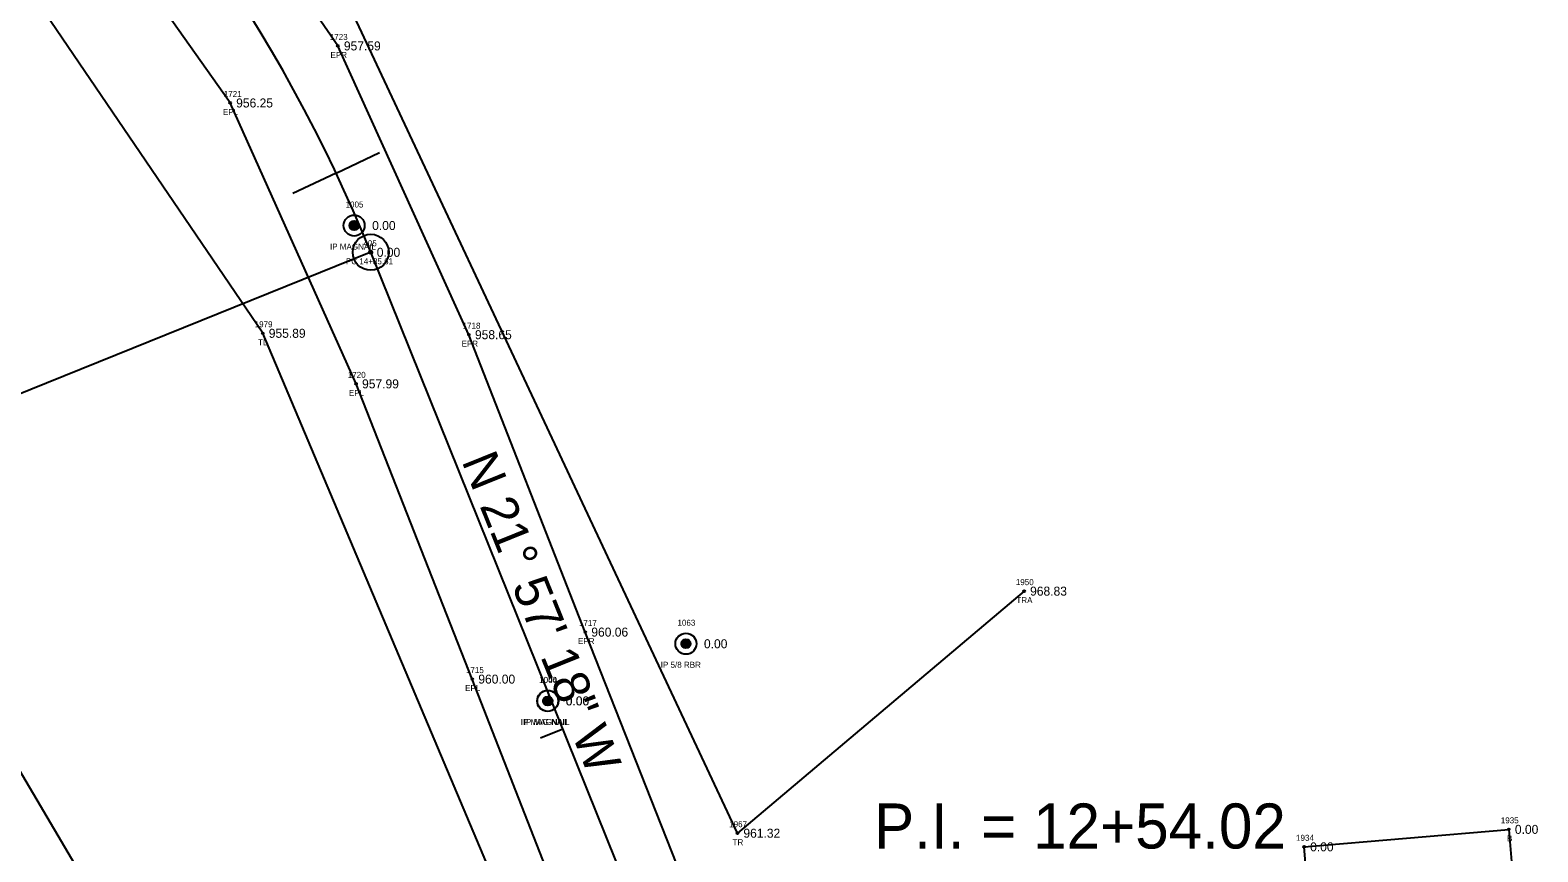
# Model space of a CAD drawing. Extents: x 1528109 to 1531398, y 1157799 to 1162548.
# Drawn here: x 1530505.4 to 1530756.6, y 1158881.4 to 1159018.3 of the extents above; entities that cross this region are included whole.
import ezdxf

# ---------------------------------------------------------------- set-up
doc = ezdxf.new("R2010")
doc.units = 0
for name, color, linetype in [('RD_EX_Bldg', 7, 'Continuous'), ('RD_EX_Bldg_txCode', 7, 'Continuous'), ('RD_EX_DV_Prop_txCode', 7, 'Continuous'), ('RD_EX_DV_PropPin', 7, 'Continuous'), ('RD_EX_Road', 7, 'Continuous'), ('RD_EX_Road_txCode', 7, 'Continuous'), ('RD_EX_TX_Bldg_ELEV', 7, 'Continuous'), ('RD_EX_TX_DV_Prop_ELEV', 7, 'Continuous'), ('RD_EX_TX_Road_ELEV', 7, 'Continuous'), ('RD_EX_TX_VEG_ELEV', 7, 'Continuous'), ('RD_EX_VEG', 7, 'Continuous'), ('RD_EX_VEG_txCode', 7, 'Continuous'), ('RD_HC_Cl', 7, 'Continuous'), ('RD_HC_Data', 7, 'Continuous'), ('RD_HC_Data_Tic', 7, 'Continuous'), ('RD_HC_Survey_ELEV', 7, 'Continuous'), ('RD_HC_txCode', 7, 'Continuous'), ('RD_SMD_Locator', 7, 'Continuous')]:
    doc.layers.add(name, color=color, linetype=linetype)

msp = doc.modelspace()

# ---------------------------------------------------------------- linework, layer by layer
at = {"layer": 'RD_EX_Bldg'}
msp.add_lwpolyline([(1530755.36, 1158841.21), (1530721.26, 1158838.3), (1530717.63, 1158882.28), (1530751.73, 1158885.19), (1530755.36, 1158841.21)], dxfattribs=at)
at = {"layer": 'RD_EX_DV_PropPin'}
for p, q in [((1530558.67, 1158985.55), (1530558.67, 1158985.94)), ((1530558.7, 1158985.45), (1530558.7, 1158986.05)), ((1530558.74, 1158985.38), (1530558.74, 1158986.12)), ((1530558.77, 1158985.32), (1530558.77, 1158986.18)), ((1530558.81, 1158985.27), (1530558.81, 1158986.22)), ((1530558.84, 1158985.23), (1530558.84, 1158986.26)), ((1530558.88, 1158985.2), (1530558.88, 1158986.3)), ((1530558.91, 1158985.17), (1530558.91, 1158986.33)), ((1530558.95, 1158985.14), (1530558.95, 1158986.36)), ((1530558.99, 1158985.11), (1530558.99, 1158986.38)), ((1530559.02, 1158985.09), (1530559.02, 1158986.4)), ((1530559.06, 1158985.07), (1530559.06, 1158986.42)), ((1530559.09, 1158985.06), (1530559.09, 1158986.44)), ((1530559.13, 1158985.04), (1530559.13, 1158986.46)), ((1530559.16, 1158985.03), (1530559.16, 1158986.47)), ((1530559.2, 1158985.02), (1530559.2, 1158986.48)), ((1530559.23, 1158985.01), (1530559.23, 1158986.49)), ((1530559.27, 1158985), (1530559.27, 1158986.5)), ((1530559.3, 1158984.99), (1530559.3, 1158986.5)), ((1530559.34, 1158984.99), (1530559.34, 1158986.51)), ((1530559.37, 1158984.99), (1530559.37, 1158986.51)), ((1530559.41, 1158984.99), (1530559.41, 1158986.51)), ((1530559.44, 1158984.99), (1530559.44, 1158986.51)), ((1530559.48, 1158984.99), (1530559.48, 1158986.51)), ((1530559.51, 1158984.99), (1530559.51, 1158986.5)), ((1530559.55, 1158985), (1530559.55, 1158986.5)), ((1530559.58, 1158985.01), (1530559.58, 1158986.49)), ((1530559.62, 1158985.02), (1530559.62, 1158986.48)), ((1530559.65, 1158985.03), (1530559.65, 1158986.47)), ((1530559.69, 1158985.04), (1530559.69, 1158986.46)), ((1530559.72, 1158985.06), (1530559.72, 1158986.44)), ((1530559.76, 1158985.07), (1530559.76, 1158986.42)), ((1530559.79, 1158985.09), (1530559.79, 1158986.4)), ((1530559.83, 1158985.11), (1530559.83, 1158986.38)), ((1530559.86, 1158985.14), (1530559.86, 1158986.36)), ((1530559.9, 1158985.17), (1530559.9, 1158986.33)), ((1530559.93, 1158985.2), (1530559.93, 1158986.3)), ((1530559.97, 1158985.23), (1530559.97, 1158986.26)), ((1530560, 1158985.27), (1530560, 1158986.22)), ((1530560.04, 1158985.32), (1530560.04, 1158986.18)), ((1530560.07, 1158985.38), (1530560.07, 1158986.12)), ((1530560.11, 1158985.45), (1530560.11, 1158986.05)), ((1530560.14, 1158985.55), (1530560.14, 1158985.94)), ((1530613.93, 1158915.9), (1530613.93, 1158916.3)), ((1530613.97, 1158915.8), (1530613.97, 1158916.4)), ((1530614, 1158915.73), (1530614, 1158916.47)), ((1530614.04, 1158915.67), (1530614.04, 1158916.53)), ((1530614.07, 1158915.63), (1530614.07, 1158916.57)), ((1530614.11, 1158915.59), (1530614.11, 1158916.62)), ((1530614.14, 1158915.55), (1530614.14, 1158916.65)), ((1530614.18, 1158915.52), (1530614.18, 1158916.68)), ((1530614.21, 1158915.49), (1530614.21, 1158916.71)), ((1530614.25, 1158915.47), (1530614.25, 1158916.74)), ((1530614.28, 1158915.44), (1530614.28, 1158916.76)), ((1530614.32, 1158915.42), (1530614.32, 1158916.78)), ((1530614.35, 1158915.41), (1530614.35, 1158916.79)), ((1530614.39, 1158915.39), (1530614.39, 1158916.81)), ((1530614.42, 1158915.38), (1530614.42, 1158916.82)), ((1530614.46, 1158915.37), (1530614.46, 1158916.83)), ((1530614.49, 1158915.36), (1530614.49, 1158916.84)), ((1530614.53, 1158915.35), (1530614.53, 1158916.85)), ((1530614.56, 1158915.35), (1530614.56, 1158916.85)), ((1530614.6, 1158915.34), (1530614.6, 1158916.86)), ((1530614.63, 1158915.34), (1530614.63, 1158916.86)), ((1530614.67, 1158915.34), (1530614.67, 1158916.86)), ((1530614.7, 1158915.34), (1530614.7, 1158916.86)), ((1530614.74, 1158915.34), (1530614.74, 1158916.86)), ((1530614.77, 1158915.35), (1530614.77, 1158916.85)), ((1530614.81, 1158915.35), (1530614.81, 1158916.85)), ((1530614.84, 1158915.36), (1530614.84, 1158916.84)), ((1530614.88, 1158915.37), (1530614.88, 1158916.83)), ((1530614.91, 1158915.38), (1530614.91, 1158916.82)), ((1530614.95, 1158915.39), (1530614.95, 1158916.81)), ((1530614.98, 1158915.41), (1530614.98, 1158916.79)), ((1530615.02, 1158915.42), (1530615.02, 1158916.78)), ((1530615.05, 1158915.44), (1530615.05, 1158916.76)), ((1530615.09, 1158915.47), (1530615.09, 1158916.74)), ((1530615.12, 1158915.49), (1530615.12, 1158916.71)), ((1530615.16, 1158915.52), (1530615.16, 1158916.68)), ((1530615.19, 1158915.55), (1530615.19, 1158916.65)), ((1530615.23, 1158915.59), (1530615.23, 1158916.62)), ((1530615.26, 1158915.63), (1530615.26, 1158916.57)), ((1530615.3, 1158915.67), (1530615.3, 1158916.53)), ((1530615.33, 1158915.73), (1530615.33, 1158916.47)), ((1530615.37, 1158915.8), (1530615.37, 1158916.4)), ((1530615.4, 1158915.9), (1530615.4, 1158916.3)), ((1530591.19, 1158905.97), (1530591.19, 1158907.19)), ((1530591.21, 1158905.97), (1530591.21, 1158907.19)), ((1530591.22, 1158905.94), (1530591.22, 1158907.21)), ((1530591.25, 1158905.95), (1530591.25, 1158907.21)), ((1530591.26, 1158905.92), (1530591.26, 1158907.24)), ((1530591.28, 1158905.92), (1530591.28, 1158907.24)), ((1530591.29, 1158905.9), (1530591.29, 1158907.26)), ((1530591.32, 1158905.9), (1530591.32, 1158907.26)), ((1530591.33, 1158905.89), (1530591.33, 1158907.27)), ((1530591.35, 1158905.89), (1530591.35, 1158907.27)), ((1530591.36, 1158905.87), (1530591.36, 1158907.29)), ((1530591.39, 1158905.87), (1530591.39, 1158907.29)), ((1530591.4, 1158905.86), (1530591.4, 1158907.3)), ((1530591.42, 1158905.86), (1530591.42, 1158907.3)), ((1530591.43, 1158905.85), (1530591.43, 1158907.31)), ((1530591.46, 1158905.85), (1530591.46, 1158907.31)), ((1530591.47, 1158905.84), (1530591.47, 1158907.32)), ((1530591.49, 1158905.84), (1530591.49, 1158907.32)), ((1530591.5, 1158905.83), (1530591.5, 1158907.33)), ((1530591.53, 1158905.83), (1530591.53, 1158907.33)), ((1530591.54, 1158905.83), (1530591.54, 1158907.33)), ((1530591.56, 1158905.83), (1530591.56, 1158907.33)), ((1530591.57, 1158905.82), (1530591.57, 1158907.34)), ((1530591.6, 1158905.82), (1530591.6, 1158907.34)), ((1530591.61, 1158905.82), (1530591.61, 1158907.34)), ((1530591.63, 1158905.82), (1530591.63, 1158907.34)), ((1530591.64, 1158905.82), (1530591.64, 1158907.34)), ((1530591.67, 1158905.82), (1530591.67, 1158907.34)), ((1530591.68, 1158905.82), (1530591.68, 1158907.34)), ((1530591.7, 1158905.82), (1530591.7, 1158907.34)), ((1530591.71, 1158905.82), (1530591.71, 1158907.34)), ((1530591.74, 1158905.82), (1530591.74, 1158907.34)), ((1530591.75, 1158905.83), (1530591.75, 1158907.33)), ((1530591.77, 1158905.83), (1530591.77, 1158907.33)), ((1530591.78, 1158905.83), (1530591.78, 1158907.33)), ((1530591.81, 1158905.83), (1530591.81, 1158907.33)), ((1530591.82, 1158905.84), (1530591.82, 1158907.32)), ((1530591.84, 1158905.84), (1530591.84, 1158907.32)), ((1530591.85, 1158905.85), (1530591.85, 1158907.31)), ((1530591.88, 1158905.85), (1530591.88, 1158907.31)), ((1530591.89, 1158905.86), (1530591.89, 1158907.3)), ((1530591.91, 1158905.86), (1530591.91, 1158907.3)), ((1530591.92, 1158905.87), (1530591.92, 1158907.29)), ((1530591.95, 1158905.87), (1530591.95, 1158907.29)), ((1530591.96, 1158905.89), (1530591.96, 1158907.27)), ((1530591.99, 1158905.89), (1530591.99, 1158907.27)), ((1530591.99, 1158905.9), (1530591.99, 1158907.26)), ((1530592.02, 1158905.9), (1530592.02, 1158907.26)), ((1530592.03, 1158905.92), (1530592.03, 1158907.24)), ((1530592.06, 1158905.92), (1530592.06, 1158907.24)), ((1530592.06, 1158905.94), (1530592.06, 1158907.21)), ((1530592.09, 1158905.95), (1530592.09, 1158907.21)), ((1530592.1, 1158905.97), (1530592.1, 1158907.19)), ((1530592.13, 1158905.97), (1530592.13, 1158907.19)), ((1530590.91, 1158906.38), (1530590.91, 1158906.78)), ((1530590.93, 1158906.38), (1530590.93, 1158906.78)), ((1530590.94, 1158906.28), (1530590.94, 1158906.88)), ((1530590.97, 1158906.28), (1530590.97, 1158906.88)), ((1530590.98, 1158906.21), (1530590.98, 1158906.95)), ((1530591, 1158906.21), (1530591, 1158906.95)), ((1530591.01, 1158906.15), (1530591.01, 1158907.01)), ((1530591.04, 1158906.15), (1530591.04, 1158907.01)), ((1530591.05, 1158906.11), (1530591.05, 1158907.05)), ((1530591.07, 1158906.11), (1530591.07, 1158907.05)), ((1530591.08, 1158906.06), (1530591.08, 1158907.09)), ((1530591.11, 1158906.06), (1530591.11, 1158907.09)), ((1530591.12, 1158906.03), (1530591.12, 1158907.13)), ((1530591.14, 1158906.03), (1530591.14, 1158907.13)), ((1530591.15, 1158906), (1530591.15, 1158907.16)), ((1530591.18, 1158906), (1530591.18, 1158907.16)), ((1530592.13, 1158906), (1530592.13, 1158907.16)), ((1530592.16, 1158906), (1530592.16, 1158907.16)), ((1530592.17, 1158906.03), (1530592.17, 1158907.13)), ((1530592.2, 1158906.03), (1530592.2, 1158907.13)), ((1530592.2, 1158906.06), (1530592.2, 1158907.09)), ((1530592.23, 1158906.06), (1530592.23, 1158907.09)), ((1530592.24, 1158906.11), (1530592.24, 1158907.05)), ((1530592.27, 1158906.11), (1530592.27, 1158907.05)), ((1530592.27, 1158906.15), (1530592.27, 1158907.01)), ((1530592.3, 1158906.15), (1530592.3, 1158907.01)), ((1530592.31, 1158906.21), (1530592.31, 1158906.95)), ((1530592.34, 1158906.21), (1530592.34, 1158906.95)), ((1530592.34, 1158906.28), (1530592.34, 1158906.88)), ((1530592.37, 1158906.28), (1530592.37, 1158906.88)), ((1530592.38, 1158906.38), (1530592.38, 1158906.78)), ((1530592.41, 1158906.38), (1530592.41, 1158906.78))]:
    msp.add_line(p, q, dxfattribs=at)
for centre, radius in [((1530559.41, 1158985.75), 1.75), ((1530559.41, 1158985.75), 0.761), ((1530614.67, 1158916.1), 1.75), ((1530614.67, 1158916.1), 0.761), ((1530591.64, 1158906.58), 1.75), ((1530591.67, 1158906.58), 1.75), ((1530591.64, 1158906.58), 0.761), ((1530591.67, 1158906.58), 0.761)]:
    msp.add_circle(centre, radius, dxfattribs=at)
at = {"layer": 'RD_EX_Road'}
for points in [[(1530704.87, 1158597.47), (1530691.01, 1158649.88), (1530681.22, 1158687.32), (1530670.59, 1158725), (1530654.42, 1158774.07), (1530635.35, 1158823.15), (1530627.8, 1158842.3), (1530617.35, 1158868.69), (1530597.91, 1158918.04), (1530578.53, 1158967.57), (1530556.7, 1159015.66), (1530524.51, 1159062.45), (1530499.94, 1159086.31), (1530481.93, 1159100.12), (1530434.53, 1159127), (1530416.95, 1159134.13), (1530380.01, 1159145.61), (1530337.52, 1159156.44)], [(1530685.41, 1158592.23), (1530678.87, 1158616.46), (1530671.67, 1158642.17), (1530661.52, 1158682.33), (1530651.17, 1158718.79), (1530644.65, 1158739.35), (1530638.95, 1158757.58), (1530635.45, 1158767.4), (1530616.88, 1158814.94), (1530597.61, 1158862.78), (1530579.09, 1158910.21), (1530559.73, 1158959.38), (1530538.76, 1159006.16), (1530508.96, 1159048.3), (1530469.44, 1159083.44), (1530424.03, 1159108.51), (1530374.97, 1159125.76), (1530332.28, 1159136.67)]]:
    msp.add_lwpolyline(points, dxfattribs=at)
at = {"layer": 'RD_EX_VEG'}
for points in [[(1530558.31, 1158802.21), (1530584.73, 1158806.6), (1530608.93, 1158749.85), (1530624.81, 1158756.88), (1530598.74, 1158838.75), (1530544.19, 1158967.8), (1530499.65, 1159033.34), (1530444.6, 1159080.15), (1530373.76, 1159115.62), (1530558.31, 1158802.21)], [(1530670.99, 1158924.86), (1530623.24, 1158884.55), (1530533.59, 1159075.66), (1530606.57, 1159106.64)]]:
    msp.add_lwpolyline(points, dxfattribs=at)
at = {"layer": 'RD_HC_Cl'}
msp.add_line((1530610.54, 1158861.31), (1530562.17, 1158981.29), dxfattribs=at)
msp.add_arc((1530329.18, 1158887.37), 251.21, 21.955, 76.0174, dxfattribs=at)
at = {"layer": 'RD_HC_Data'}
msp.add_line((1530562.17, 1158981.29), (1530454.54, 1158937.9), dxfattribs=at)
for radius in [3, 0.282]:
    msp.add_circle((1530562.17, 1158981.29), radius, dxfattribs=at)
at = {"layer": 'RD_HC_Data_Tic'}
for p, q in [((1530556.41, 1158994.48), (1530563.65, 1158997.89)), ((1530556.41, 1158994.48), (1530549.18, 1158991.07)), ((1530594.18, 1158901.89), (1530590.47, 1158900.4))]:
    msp.add_line(p, q, dxfattribs=at)
at = {"layer": 'RD_SMD_Locator'}
for centre in [(1530556.7, 1159015.66), (1530538.76, 1159006.16), (1530559.41, 1158985.75), (1530562.17, 1158981.29), (1530544.19, 1158967.8), (1530578.53, 1158967.57), (1530559.73, 1158959.38), (1530670.99, 1158924.86), (1530597.91, 1158918.04), (1530614.67, 1158916.1), (1530579.09, 1158910.21), (1530591.64, 1158906.58), (1530591.67, 1158906.58), (1530623.24, 1158884.55), (1530751.73, 1158885.19), (1530717.63, 1158882.28)]:
    msp.add_circle(centre, 0.15, dxfattribs=at)

# ---------------------------------------------------------------- texts
at = {"layer": 'RD_EX_Bldg_txCode'}
for s, p in [('1935', (1530750.38, 1158886.19)), ('1934', (1530716.28, 1158883.28)), ('B', (1530751.42, 1158883.19))]:
    msp.add_text(s, height=1, dxfattribs=at).set_placement(p)
at = {"layer": 'RD_EX_DV_Prop_txCode'}
for s, p in [('1005', (1530557.98, 1158988.75)), ('IP MAGNAIL', (1530555.39, 1158981.75)), ('1063', (1530613.26, 1158919.1)), ('IP 5/8 RBR', (1530610.47, 1158912.1)), ('1040', (1530590.22, 1158909.58)), ('1004', (1530590.24, 1158909.58)), ('IP MAG NAIL', (1530587.15, 1158902.58)), ('IP MAGNAIL', (1530587.65, 1158902.58))]:
    msp.add_text(s, height=1, dxfattribs=at).set_placement(p)
at = {"layer": 'RD_EX_Road_txCode'}
for s, p in [('1723', (1530555.35, 1159016.66)), ('EPR', (1530555.47, 1159013.66)), ('1721', (1530537.7, 1159007.16)), ('EPL', (1530537.55, 1159004.16)), ('1718', (1530577.47, 1158968.57)), ('EPR', (1530577.3, 1158965.57)), ('1720', (1530558.35, 1158960.38)), ('EPL', (1530558.53, 1158957.38)), ('1717', (1530596.85, 1158919.04)), ('EPR', (1530596.69, 1158916.04)), ('1715', (1530578.03, 1158911.21)), ('EPL', (1530577.89, 1158908.21))]:
    msp.add_text(s, height=1, dxfattribs=at).set_placement(p)
at = {"layer": 'RD_EX_TX_Bldg_ELEV'}
for p in [(1530752.73, 1158884.44), (1530718.63, 1158881.53)]:
    msp.add_text('0.00', height=1.5, dxfattribs=at).set_placement(p)
at = {"layer": 'RD_EX_TX_DV_Prop_ELEV'}
for p in [(1530562.41, 1158985), (1530617.67, 1158915.35), (1530594.64, 1158905.83), (1530594.67, 1158905.83)]:
    msp.add_text('0.00', height=1.5, dxfattribs=at).set_placement(p)
at = {"layer": 'RD_EX_TX_Road_ELEV'}
for s, p in [('957.59', (1530557.7, 1159014.91)), ('956.25', (1530539.76, 1159005.41)), ('958.65', (1530579.53, 1158966.82)), ('957.99', (1530560.73, 1158958.63)), ('960.06', (1530598.91, 1158917.29)), ('960.00', (1530580.09, 1158909.46))]:
    msp.add_text(s, height=1.5, dxfattribs=at).set_placement(p)
at = {"layer": 'RD_EX_TX_VEG_ELEV'}
for s, p in [('955.89', (1530545.19, 1158967.05)), ('968.83', (1530671.99, 1158924.11)), ('961.32', (1530624.24, 1158883.8))]:
    msp.add_text(s, height=1.5, dxfattribs=at).set_placement(p)
at = {"layer": 'RD_EX_VEG_txCode'}
for s, p in [('1979', (1530542.84, 1158968.8)), ('TL', (1530543.41, 1158965.8)), ('1950', (1530669.61, 1158925.86)), ('TRA', (1530669.71, 1158922.86)), ('1967', (1530621.87, 1158885.55)), ('TR', (1530622.44, 1158882.55))]:
    msp.add_text(s, height=1, dxfattribs=at).set_placement(p)
at = {"layer": 'RD_HC_Data'}
msp.add_text('N 21%%d 57\' 18" W', height=6, rotation=291.955, dxfattribs=at).set_placement((1530577.26, 1158946.54))
msp.add_text('P.I. = 12+54.02', height=7.5, dxfattribs=at).set_placement((1530646, 1158882))
at = {"layer": 'RD_HC_Survey_ELEV'}
msp.add_text('0.00', height=1.5, dxfattribs=at).set_placement((1530563.18, 1158980.54))
at = {"layer": 'RD_HC_txCode'}
for s, p in [('405', (1530560.95, 1158982.29)), ('PC 14+85.61', (1530558.04, 1158979.29))]:
    msp.add_text(s, height=1, dxfattribs=at).set_placement(p)

doc.saveas('drawing.dxf')
